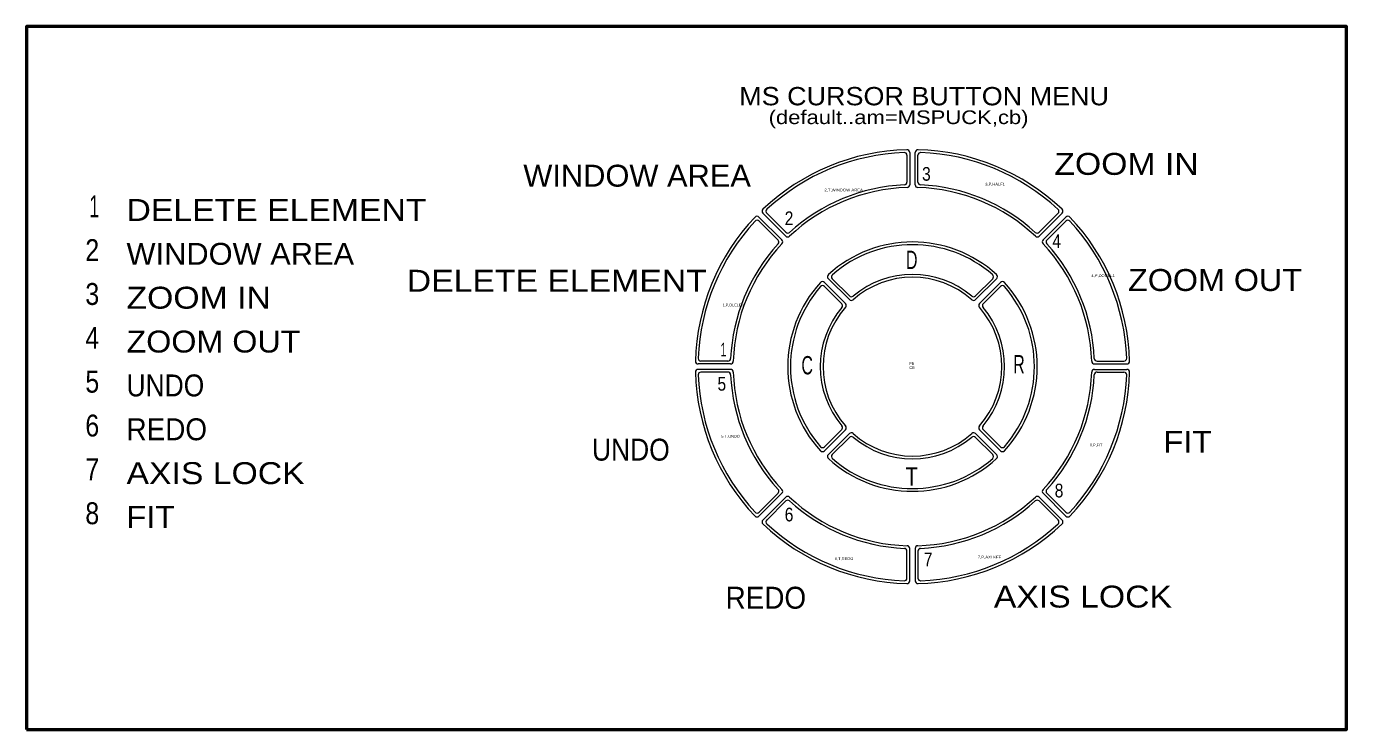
# Model space of a CAD drawing. Extents: x 1589.52 to 1594.53, y 1591.1 to 1593.78.
import ezdxf
from ezdxf.enums import TextEntityAlignment as Align

# ---------------------------------------------------------------- set-up
doc = ezdxf.new("R2010")
doc.units = 0
doc.header["$LTSCALE"] = 0.033
doc.layers.add('1', color=7, linetype='Continuous', lineweight=13)
doc.layers.add('10', color=7, linetype='Continuous', lineweight=13)
doc.layers.add('4', color=7, linetype='Continuous')
doc.layers.add('63', color=7, linetype='Continuous')

msp = doc.modelspace()

# ---------------------------------------------------------------- linework, layer by layer
at = {"layer": '1'}
for p, q in [((1592.86532, 1593.28687), (1592.86532, 1593.18462)), ((1592.87574, 1593.29764), (1592.87574, 1593.17459)), ((1592.89657, 1593.17459), (1592.89657, 1593.29764)), ((1592.90699, 1593.18462), (1592.90699, 1593.28687)), ((1592.39017, 1592.96483), (1592.30317, 1593.05183)), ((1592.40491, 1592.97957), (1592.31791, 1593.06657)), ((1592.40519, 1592.99404), (1592.33289, 1593.06634)), ((1593.43945, 1593.06633), (1593.36715, 1592.99403)), ((1593.45442, 1593.06657), (1593.36741, 1592.97956)), ((1593.46916, 1593.05183), (1593.38215, 1592.96482)), ((1592.37571, 1592.96456), (1592.30341, 1593.03686)), ((1593.46892, 1593.03686), (1593.39661, 1592.96456)), ((1592.63166, 1592.72334), (1592.55155, 1592.80345)), ((1592.56629, 1592.81819), (1592.6464, 1592.73808)), ((1592.58146, 1592.81775), (1592.64692, 1592.75229)), ((1593.19086, 1592.81775), (1593.12541, 1592.75229)), ((1593.20602, 1592.81818), (1593.12593, 1592.73808)), ((1593.14067, 1592.72334), (1593.22076, 1592.80344)), ((1592.61745, 1592.72282), (1592.55199, 1592.78828)), ((1593.15487, 1592.72282), (1593.22033, 1592.78828)), ((1592.1851, 1592.50441), (1592.08285, 1592.50441)), ((1593.58721, 1592.50441), (1593.68946, 1592.50441)), ((1592.19514, 1592.49399), (1592.07209, 1592.49399)), ((1592.19514, 1592.47316), (1592.07209, 1592.47316)), ((1592.1851, 1592.46274), (1592.08285, 1592.46274)), ((1593.57718, 1592.49399), (1593.70022, 1592.49399)), ((1593.57718, 1592.47316), (1593.70022, 1592.47316)), ((1593.58721, 1592.46274), (1593.68946, 1592.46274)), ((1592.63165, 1592.2438), (1592.55155, 1592.16371)), ((1592.61744, 1592.24432), (1592.55198, 1592.17886)), ((1592.56629, 1592.14896), (1592.6464, 1592.22906)), ((1592.58146, 1592.1494), (1592.64692, 1592.21485)), ((1593.19086, 1592.1494), (1593.12541, 1592.21485)), ((1593.20602, 1592.14897), (1593.12593, 1592.22906)), ((1593.22077, 1592.16371), (1593.14067, 1592.24381)), ((1593.22033, 1592.17887), (1593.15487, 1592.24433)), ((1592.39017, 1592.00232), (1592.30316, 1591.91531)), ((1592.3757, 1592.00258), (1592.3034, 1591.93028)), ((1593.38216, 1592.00232), (1593.46916, 1591.91532)), ((1593.39661, 1592.00259), (1593.46892, 1591.93029)), ((1592.40491, 1591.98757), (1592.31791, 1591.90057)), ((1592.40519, 1591.9731), (1592.33289, 1591.9008)), ((1593.43945, 1591.90081), (1593.36715, 1591.97311)), ((1593.45442, 1591.90057), (1593.36741, 1591.98758)), ((1592.86532, 1591.68027), (1592.86532, 1591.78252)), ((1592.87574, 1591.66951), (1592.87574, 1591.79255)), ((1592.89657, 1591.79255), (1592.89657, 1591.66951)), ((1592.90699, 1591.78252), (1592.90699, 1591.68027))]:
    msp.add_line(p, q, dxfattribs=at)
at = {"layer": '1', "lineweight": 53}
msp.add_lwpolyline([(1589.52092, 1591.10428), (1594.53492, 1591.10428), (1594.53492, 1593.77654), (1589.52092, 1593.77654)], close=True, dxfattribs=at)
msp.add_lwpolyline([(1589.52092, 1591.10428), (1594.53492, 1591.10428), (1594.53492, 1593.77654), (1589.52092, 1593.77654)], close=True, dxfattribs=at)
at = {"layer": '1'}
for centre, radius, start, end in [((1592.88616, 1592.48357), 0.82474, 91.46599, 133.53309), ((1592.86532, 1593.29763), 0.01042, 0, 91.46599), ((1592.90699, 1593.29763), 0.01042, 88.53401, 180), ((1592.88616, 1592.48357), 0.82474, 46.46106, 88.59887), ((1592.88616, 1592.48357), 0.81433, 92.22779, 132.77033), ((1592.85491, 1593.28688), 0.01042, 0, 92.22779), ((1592.91741, 1593.28688), 0.01042, 87.77221, 180), ((1592.88616, 1592.48357), 0.81433, 47.22851, 87.82053), ((1592.88616, 1592.48357), 0.68092, 91.727, 133.27177), ((1592.88616, 1592.48357), 0.69133, 92.55191, 132.44564), ((1592.85491, 1593.18463), 0.01042, 272.55231, 0), ((1592.86532, 1593.17459), 0.01042, 271.72687, 0), ((1592.90699, 1593.17459), 0.01042, 180, 268.27313), ((1592.88616, 1592.48357), 0.68092, 46.72735, 88.27313), ((1592.91741, 1593.18463), 0.01042, 180, 267.44769), ((1592.88616, 1592.48357), 0.69133, 47.55266, 87.44769), ((1592.2958, 1593.04447), 0.01042, 45, 136.46587), ((1592.32527, 1593.07394), 0.01042, 133.53309, 225), ((1592.34025, 1593.07371), 0.01042, 132.77033, 225), ((1593.43208, 1593.07369), 0.01042, 315, 47.22809), ((1593.44705, 1593.07394), 0.01042, 315, 46.46639), ((1593.47652, 1593.04447), 0.01042, 43.53361, 135), ((1592.29604, 1593.0295), 0.01042, 45, 137.22757), ((1593.47628, 1593.02949), 0.01042, 42.77191, 135), ((1592.36834, 1592.9572), 0.01042, 317.55206, 45), ((1592.3828, 1592.95747), 0.01042, 316.72674, 45), ((1592.41227, 1592.98694), 0.01042, 225, 313.27204), ((1592.41255, 1593.00141), 0.01042, 225, 312.44554), ((1593.35978, 1593.00139), 0.01042, 227.55266, 315), ((1593.36005, 1592.98693), 0.01042, 226.72735, 315), ((1593.38952, 1592.95746), 0.01042, 135, 223.27265), ((1593.40398, 1592.95719), 0.01042, 135, 222.44734), ((1592.54419, 1592.79608), 0.01042, 45, 137.57739), ((1592.57366, 1592.82555), 0.01042, 132.42079, 225), ((1592.58882, 1592.82512), 0.01042, 131.04141, 225), ((1593.18349, 1592.82511), 0.01042, 315, 48.95766), ((1593.19866, 1592.82554), 0.01042, 315, 47.5783), ((1593.22813, 1592.79607), 0.01042, 42.4217, 135), ((1592.54462, 1592.78092), 0.01042, 45, 138.95673), ((1592.65428, 1592.75966), 0.01042, 225, 310.02579), ((1593.11804, 1592.75965), 0.01042, 229.97303, 315), ((1593.22769, 1592.78091), 0.01042, 41.04234, 135), ((1592.61008, 1592.71546), 0.01042, 319.97186, 45), ((1592.62429, 1592.71598), 0.01042, 318.411, 45), ((1592.65376, 1592.74545), 0.01042, 225, 311.58658), ((1593.11856, 1592.74545), 0.01042, 228.41221, 315), ((1593.14803, 1592.71597), 0.01042, 135, 221.58779), ((1593.16224, 1592.71545), 0.01042, 135, 220.02697), ((1592.0721, 1592.50441), 0.01042, 178.53401, 270), ((1592.08285, 1592.51482), 0.01042, 177.77221, 270), ((1592.1851, 1592.51482), 0.01042, 270, 357.44769), ((1592.19514, 1592.50441), 0.01042, 270, 358.27313), ((1593.57718, 1592.50441), 0.01042, 181.72687, 270), ((1593.58721, 1592.51482), 0.01042, 182.55231, 270), ((1593.68946, 1592.51482), 0.01042, 270, 2.22779), ((1593.70022, 1592.50441), 0.01042, 270, 1.46599), ((1592.0721, 1592.46274), 0.01042, 90, 181.46599), ((1592.08285, 1592.45232), 0.01042, 90, 182.22779), ((1592.1851, 1592.45232), 0.01042, 2.55231, 90), ((1592.19514, 1592.46274), 0.01042, 1.72687, 90), ((1593.57718, 1592.46274), 0.01042, 90, 178.27313), ((1593.58721, 1592.45232), 0.01042, 90, 177.44769), ((1593.68946, 1592.45232), 0.01042, 357.77221, 90), ((1593.70022, 1592.46274), 0.01042, 358.53401, 90), ((1592.61007, 1592.25169), 0.01042, 315, 40.02697), ((1592.62428, 1592.25117), 0.01042, 315, 41.58779), ((1593.14803, 1592.25118), 0.01042, 138.41342, 225), ((1593.16224, 1592.2517), 0.01042, 139.97421, 225), ((1592.65376, 1592.2217), 0.01042, 48.41342, 135), ((1592.65428, 1592.20749), 0.01042, 49.97421, 135), ((1593.11804, 1592.20749), 0.01042, 45, 130.02697), ((1593.11856, 1592.2217), 0.01042, 45, 131.58779), ((1592.54419, 1592.17107), 0.01042, 222.4217, 315), ((1592.54462, 1592.18624), 0.01042, 221.04234, 315), ((1592.57366, 1592.1416), 0.01042, 135, 227.57921), ((1592.58882, 1592.14203), 0.01042, 135, 228.95859), ((1593.18349, 1592.14203), 0.01042, 311.04234, 45), ((1593.19866, 1592.1416), 0.01042, 312.4217, 45), ((1593.2277, 1592.18624), 0.01042, 225, 318.95859), ((1593.22813, 1592.17108), 0.01042, 225, 317.57921), ((1592.36834, 1592.00995), 0.01042, 315, 42.44734), ((1592.3828, 1592.00968), 0.01042, 315, 43.27265), ((1593.38952, 1592.00969), 0.01042, 136.72796, 225), ((1593.40398, 1592.00996), 0.01042, 137.55326, 225), ((1592.41227, 1591.98021), 0.01042, 46.72796, 135), ((1592.41255, 1591.96574), 0.01042, 47.55446, 135), ((1592.88616, 1592.48357), 0.68092, 226.72823, 268.273), ((1592.88616, 1592.48357), 0.69133, 227.55436, 267.44809), ((1592.88616, 1592.48357), 0.68092, 271.72687, 313.27265), ((1592.88616, 1592.48357), 0.69133, 272.55231, 312.44734), ((1593.35978, 1591.96575), 0.01042, 45, 132.44734), ((1593.36005, 1591.98021), 0.01042, 45, 133.27265), ((1592.29579, 1591.92268), 0.01042, 223.53361, 315), ((1592.29604, 1591.93765), 0.01042, 222.77191, 315), ((1592.32527, 1591.8932), 0.01042, 135, 226.46691), ((1592.34025, 1591.89344), 0.01042, 135, 227.22967), ((1593.43208, 1591.89345), 0.01042, 312.77191, 45), ((1593.44705, 1591.89321), 0.01042, 313.53361, 45), ((1593.47628, 1591.93766), 0.01042, 225, 317.22862), ((1593.47652, 1591.92269), 0.01042, 225, 316.46691), ((1592.88616, 1592.48357), 0.82474, 226.46691, 268.53401), ((1592.88616, 1592.48357), 0.81433, 227.22967, 267.77221), ((1592.88616, 1592.48357), 0.82474, 271.40113, 313.53894), ((1592.88616, 1592.48357), 0.81433, 272.17947, 312.77149), ((1592.86532, 1591.79255), 0.01042, 0, 88.27313), ((1592.90699, 1591.79255), 0.01042, 91.72687, 180), ((1592.85491, 1591.78252), 0.01042, 0, 87.44769), ((1592.91741, 1591.78252), 0.01042, 92.55231, 180), ((1592.85491, 1591.68027), 0.01042, 267.77221, 0), ((1592.86532, 1591.66951), 0.01042, 268.53401, 0), ((1592.90699, 1591.66951), 0.01042, 180, 271.46599), ((1592.91741, 1591.68027), 0.01042, 180, 272.22779)]:
    msp.add_arc(centre, radius, start, end, dxfattribs=at)
at = {"layer": '10'}
for radius, start, end in [(0.82474, 136.46588, 178.53401), (0.82474, 1.46599, 43.5333), (0.81433, 137.22757, 177.77221), (0.81433, 2.19928, 42.80053), (0.69133, 137.55192, 177.44809), (0.68092, 136.72699, 178.273), (0.47367, 47.57756, 132.42066), (0.68092, 1.72687, 43.27265), (0.69133, 2.55231, 42.44734), (0.46325, 48.86849, 131.04218), (0.47367, 137.57739, 222.42244), (0.33971, 48.41221, 131.58656), (0.35013, 49.97303, 130.02535), (0.47367, 317.57921, 42.47856), (0.46325, 138.95673, 221.04219), (0.46325, 318.95859, 41.04218), (0.35013, 139.97225, 220.02697), (0.33971, 138.41096, 221.58779), (0.33971, 318.41344, 41.58779), (0.35013, 319.97465, 40.02697), (0.81433, 2.19901, 2.22779), (0.82474, 181.46628, 223.5333), (0.81433, 182.19928, 222.77149), (0.69133, 182.55231, 222.44734), (0.68092, 181.72687, 223.27265), (0.68092, 316.72823, 358.273), (0.69133, 317.55314, 357.44809), (0.81433, 317.22862, 357.77221), (0.82474, 316.46691, 358.53401), (0.33971, 228.41344, 311.58779), (0.35013, 229.97465, 310.02697), (0.47367, 227.57934, 312.42244), (0.46325, 228.95782, 311.13151)]:
    msp.add_arc((1592.88616, 1592.48357), radius, start, end, dxfattribs=at)

# ---------------------------------------------------------------- texts
at = {"layer": '1'}
for s, height, width, p in [('(default..am=MSPUCK,cb)', 0.05208, 1.2, (1592.33985, 1593.40524)), ('WINDOW AREA', 0.08333, 1.05, (1591.40811, 1593.16751)), ('ZOOM IN', 0.08333, 1.15, (1593.42491, 1593.21229)), ('3', 0.05208, 0.85, (1592.92246, 1593.18992)), ('DELETE ELEMENT', 0.08333, 1.15, (1589.90111, 1593.03721)), ('2', 0.05208, 0.85, (1592.40084, 1593.02128)), ('WINDOW AREA', 0.08333, 1.05, (1589.90111, 1592.87054)), ('4', 0.05208, 0.85, (1593.41744, 1592.93469)), ('DELETE ELEMENT', 0.08333, 1.15, (1590.96553, 1592.7683)), ('ZOOM OUT', 0.08333, 1.1, (1593.70502, 1592.77112)), ('ZOOM IN', 0.08333, 1.15, (1589.90111, 1592.70387)), ('ZOOM OUT', 0.08333, 1.1, (1589.90111, 1592.53721)), ('1', 0.05208, 0.6, (1592.15668, 1592.52222)), ('UNDO', 0.08333, 0.9, (1589.90111, 1592.37054)), ('5', 0.05208, 0.85, (1592.14558, 1592.39232)), ('REDO', 0.08333, 0.95, (1589.90111, 1592.20387)), ('UNDO', 0.08333, 0.9, (1591.66897, 1592.12651)), ('FIT', 0.08333, 1.1, (1593.83948, 1592.15628)), ('AXIS LOCK', 0.08333, 1.15, (1589.90111, 1592.03721)), ('8', 0.05208, 0.85, (1593.42631, 1591.98669)), ('FIT', 0.08333, 1.1, (1589.90111, 1591.87054)), ('6', 0.05208, 0.85, (1592.40084, 1591.89553)), ('7', 0.05208, 0.85, (1592.92911, 1591.72462)), ('REDO', 0.08333, 0.95, (1592.17634, 1591.56379)), ('AXIS LOCK', 0.08333, 1.15, (1593.19522, 1591.5681))]:
    msp.add_text(s, height=height, dxfattribs=dict(at, width=width)).set_placement(p)
for s, width, p in [('1', 0.6, (1589.79745, 1593.05136)), ('2', 0.85, (1589.79746, 1592.88471)), ('3', 0.85, (1589.79746, 1592.71805)), ('4', 0.85, (1589.79746, 1592.5514)), ('5', 0.85, (1589.79746, 1592.38474)), ('6', 0.85, (1589.79746, 1592.21808)), ('7', 0.85, (1589.79746, 1592.05143)), ('8', 0.85, (1589.79746, 1591.88477))]:
    msp.add_text(s, height=0.08333, dxfattribs=dict(at, width=width)).set_placement(p, align=Align.RIGHT)
at = {"layer": '4'}
for s, width, p in [('MS CURSOR BUTTON MENU', 1.1, (1592.22811, 1593.47664)), ('D', 0.65, (1592.86146, 1592.85453)), ('C', 0.65, (1592.46432, 1592.45419)), ('R', 0.65, (1593.26871, 1592.45786)), ('T', 0.8, (1592.86036, 1592.0318))]:
    msp.add_text(s, height=0.06958, dxfattribs=dict(at, width=width)).set_placement(p)
at = {"layer": '63'}
for s, width, p in [('2,T,WINDOW AREA', 1.15, (1592.55172, 1593.14949)), ('3,P,HALF1', 1.1, (1593.16236, 1593.1719)), ('4,P,DOUBL1', 1.1, (1593.56573, 1592.82455)), ('FB', 0.95, (1592.87444, 1592.49031)), ('CB', 0.9, (1592.87444, 1592.47469)), ('5,T,UNDO', 1.1, (1592.15956, 1592.21392)), ('6,T,REDO', 1.1, (1592.59094, 1591.74893)), ('7,P,AXLKFF', 1.15, (1593.13435, 1591.75453))]:
    msp.add_text(s, height=0.01042, dxfattribs=dict(at, width=width)).set_placement(p)
for s, p in [('1,P,DLELEM', (1592.16517, 1592.71251)), ('8,P,FIT', (1593.56012, 1592.1803))]:
    msp.add_text(s, height=0.01042, dxfattribs=at).set_placement(p)

doc.saveas('drawing.dxf')
